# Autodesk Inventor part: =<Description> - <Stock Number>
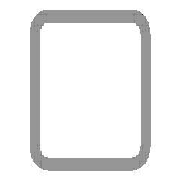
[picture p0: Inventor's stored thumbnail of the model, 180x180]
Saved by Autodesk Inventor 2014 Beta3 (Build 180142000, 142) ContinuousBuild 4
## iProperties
IsCustomPart: 1
_CCFamilyMember: 9
_CCFamilyDisplayName: ANSI AISC (Square) - Tube
_FrameMemberDoc: Frame Member File
_Version: 15.0.0
_GetPNFromCC: 1
Created: 2011-01
Part Number: =<Description> - <Stock Number>
Material: Steel, Mild
Description: Tube
Document SubType Name: Modeling
Standard: ANSI
Designer: Beta-8540w
Standards Organization: ANSI
Language: en-US
Size Designation: 3x3x3/16
Categories: <MemberInstance><Categories><Category DisplayName="Structural Shapes" InternalName="089c4875-fa83-4c05-b084-43b9cc11f5ed" Mnemonic="GRDR"><CategoryParameter Dis
Stock Number: 3x3x3/16
Density: 7.86 g/cm^3
Appearance: Steel
G_L: 58.775 in
G_W: 3.000 in
G_H: 3.000 in
+F1DD31D7-8EA7-4030-B73F-B4109CE49B1F+CUTDETAIL1: Cut
Author: Beta-8540w
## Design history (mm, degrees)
node "Start plane"
node "End plane"
sketch "Sketch"
  geometry: L1 (-38.1, -28.575)-(-38.1, 28.575); L2 (-28.575, 38.1)-(28.575, 38.1); L3 (38.1, 28.575)-(38.1, -28.575); L4 (28.575, -38.1)-(-28.575, -38.1); L5 (-28.575, 33.337)-(28.575, 33.338); L6 (33.338, 28.575)-(33.338, -28.575); L7 (28.575, -33.337)-(-28.575, -33.338); L8 (-33.338, -28.575)-(-33.338, 28.575); L9 (0, 56.102)-(0, -56.102) reference; L10 (-56.102, 0)-(56.102, 0) reference; A1 r 9.525 centre (-28.575, -28.575) between (-38.1, -28.575) and (-28.575, -38.1); A2 r 9.525 centre (-28.575, 28.575) between (-28.575, 38.1) and (-38.1, 28.575); A3 r 9.525 centre (28.575, 28.575) between (38.1, 28.575) and (28.575, 38.1); A4 r 9.525 centre (28.575, -28.575) between (28.575, -38.1) and (38.1, -28.575); A5 r 4.763 centre (-28.575, 28.575) between (-28.575, 33.337) and (-33.338, 28.575); A6 r 4.763 centre (28.575, 28.575) between (33.338, 28.575) and (28.575, 33.338); A7 r 4.763 centre (28.575, -28.575) between (28.575, -33.337) and (33.338, -28.575); A8 r 4.763 centre (-28.575, -28.575) between (-33.338, -28.575) and (-28.575, -33.338)
  constraints: 16 end point, 16 point on circle, 8 centre point, 8 tangent, 4 parallel, 3 equal radius, 2 perpendicular, 7 other
  dimensions: "d10" = 76.2 distance between parallel lines of L2 L4 (= G_H); "d11" = 76.2 distance between parallel lines of L1 L3 (= G_W); "d12" = 4.7625 distance between parallel lines of L3 L6 (= G_T); "d15" = 38.1 distance between parallel lines of L2 L10 (= 0.5 x d10); "d16" = 38.1 distance between parallel lines of L9 L3 (= 0.5 x d11); "d17" = 9.525 radius of A1 (= G_IR)
extrude "Body" new body sketch "Sketch" stored distance "d3" = 1492.89148 (= G_L); taper "d4" = 0 deg
node "Driven Length"
  sketch "Sketch3"
    geometry: L1 (0, 0)-(10, 0) reference
    constraints: 2 end point, 1 horizontal
  workplane "Work Plane3"
  sketch "Sketch4"
    geometry: L1 (-2, 31.109)-(12, 31.109) reference; L2 (-2, 1524)-(12, 1524) reference
    dimensions: "d19" = 1492.89148 distance between parallel lines of L1 L2 (derived)
workplane "Work Plane4"
split "Split1"
body "Solid1"
other parameters: "G_W" = 76.2 [user parameter; used in 1 equation term], "G_H" = 76.2 [user parameter; used in 1 equation term], "G_T" = 4.7625 [user parameter; used in 1 equation term], "G_IR" = 9.525 [user parameter; used in 1 equation term], "G_L" = 1492.89148 (= d19) [user parameter; used in 1 equation term], "G_OFFSET_START" = -31.10852 [user parameter; used in 1 equation term], "G_OFFSET_END" = 0 [user parameter; used in 1 equation term], "d13" = 31.10852 (= -G_OFFSET_START), "d14" = 1524 (= G_OFFSET_END + B_L), "B_L" = 1524 [user parameter; used in 1 equation term], "d18" = 90 deg
